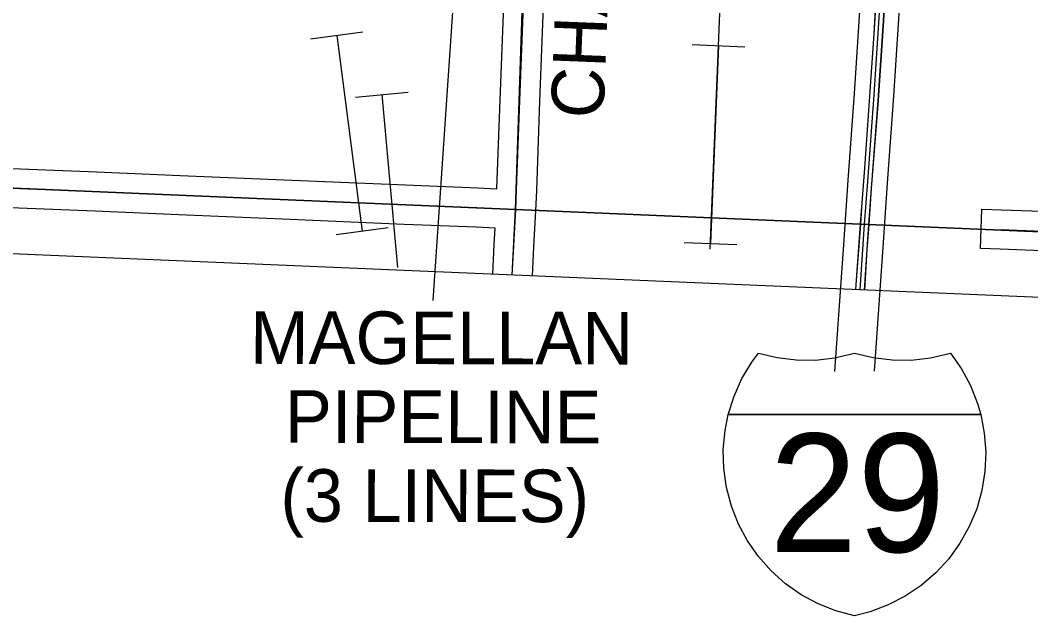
# Model space of a CAD drawing. Extents: x -157.2 to -99.3, y 12.2 to 46.2.
# Drawn here: x -141.844 to -140.306, y 16.458 to 17.364 of the extents above; entities that cross this region are included whole.
import ezdxf

# ---------------------------------------------------------------- set-up
doc = ezdxf.new("R2010")
doc.units = 0
for name, color, linetype in [('tdCoClipBndry', 7, 'Continuous'), ('tdCoCoBndry', 7, 'Continuous'), ('tdCoCoBndryPart', 7, 'Continuous'), ('tdCoDivCarto', 7, 'Continuous'), ('tdCoInt', 7, 'Continuous'), ('tdCoIntCL', 7, 'Continuous'), ('tdCoIntRte', 7, 'Continuous'), ('tdCoPipe', 7, 'Continuous'), ('tdCoPipe1', 7, 'Continuous'), ('tdCoPipe2', 7, 'Continuous'), ('tdCoPipeTxt', 7, 'Continuous'), ('tdCoSecRdTxt', 7, 'Continuous'), ('tdCoSecRteBand', 7, 'Continuous'), ('tdCoSecRteCL', 7, 'Continuous'), ('tdCoSectLine', 7, 'Continuous'), ('tdCoSectLinePart', 7, 'Continuous'), ('tdCoShieldInt', 7, 'Continuous'), ('tdCoSurfAsphalt', 7, 'Continuous'), ('tdCoSurfConc', 7, 'Continuous'), ('tdCoSurfEarth', 7, 'Continuous'), ('tdCoSurfGravel', 7, 'Continuous'), ('tdCoTwpBndryShd', 7, 'Continuous')]:
    doc.layers.add(name, color=color, linetype=linetype)

msp = doc.modelspace()

# ---------------------------------------------------------------- linework, layer by layer
at = {"layer": 'tdCoClipBndry'}
msp.add_lwpolyline([(-136.1344, 16.7663), (-142.0845, 17.0183), (-145.0729, 17.1202)], dxfattribs=at)
at = {"layer": 'tdCoCoBndry'}
msp.add_lwpolyline([(-146.5016, 17.2735), (-146.0768, 17.2556), (-146.0694, 17.2557), (-145.0695, 17.2201), (-144.0702, 17.1857), (-143.0731, 17.1519), (-142.0807, 17.1182), (-141.0904, 17.0763), (-140.1006, 17.0343), (-139.109, 16.9941), (-138.1248, 16.9495), (-137.1248, 16.9061), (-136.1296, 16.8661), (-135.1553, 16.8138), (-134.1666, 16.7512)], dxfattribs=at)
at = {"layer": 'tdCoCoBndryPart'}
msp.add_lwpolyline([(-140.5475, 17.0533), (-140.3822, 17.0463)], dxfattribs=at)
at = {"layer": 'tdCoDivCarto'}
for points in [[(-140.5562, 17.7668), (-140.5483, 17.6739), (-140.5424, 17.6039), (-140.5382, 17.5521), (-140.5372, 17.5151), (-140.5367, 17.4766), (-140.5392, 17.4325), (-140.5414, 17.3999), (-140.5449, 17.3435), (-140.5505, 17.2631), (-140.5592, 17.139), (-140.5631, 17.0865)], [(-140.5562, 17.7668), (-140.5483, 17.6739), (-140.5424, 17.6039), (-140.5382, 17.5521), (-140.5372, 17.5151), (-140.5367, 17.4766), (-140.5392, 17.4325), (-140.5414, 17.3999), (-140.5449, 17.3435), (-140.5505, 17.2631), (-140.5592, 17.139), (-140.5631, 17.0865)], [(-140.5523, 17.0533), (-140.5523, 17.0535), (-140.5484, 17.1082), (-140.5382, 17.2422), (-140.5298, 17.363), (-140.5261, 17.4301), (-140.5236, 17.4666), (-140.5234, 17.4992), (-140.5239, 17.5305), (-140.5251, 17.5583), (-140.5315, 17.6336), (-140.5423, 17.7657), (-140.5425, 17.768)], [(-140.5523, 17.0533), (-140.5523, 17.0535), (-140.5484, 17.1082), (-140.5382, 17.2422), (-140.5298, 17.363), (-140.5261, 17.4301), (-140.5236, 17.4666), (-140.5234, 17.4992), (-140.5239, 17.5305), (-140.5251, 17.5583), (-140.5315, 17.6336), (-140.5423, 17.7657), (-140.5425, 17.768)], [(-140.5631, 17.0865), (-140.5655, 17.0543)], [(-140.5631, 17.0865), (-140.5655, 17.0543)], [(-140.5655, 17.0543), (-140.5655, 17.054), (-140.5723, 16.962), (-140.5728, 16.9543)], [(-140.5655, 17.0543), (-140.5655, 17.054), (-140.5723, 16.962), (-140.5728, 16.9543)], [(-140.559, 16.9537), (-140.555, 17.0154), (-140.5523, 17.0533)], [(-140.559, 16.9537), (-140.555, 17.0154), (-140.5523, 17.0533)]]:
    msp.add_lwpolyline(points, dxfattribs=at)
at = {"layer": 'tdCoInt'}
for points in [[(-140.6042, 16.8299), (-140.5903, 17.0302), (-140.584, 17.1207), (-140.5744, 17.2528), (-140.5628, 17.4333), (-140.5599, 17.4735), (-140.5597, 17.501), (-140.5604, 17.5202), (-140.5618, 17.5511), (-140.5795, 17.7648), (-140.5873, 17.8534), (-140.5902, 17.8858), (-140.5991, 17.9892)], [(-140.544, 16.8304), (-140.5304, 17.026), (-140.5242, 17.1164), (-140.5145, 17.2487), (-140.5029, 17.4293), (-140.4999, 17.4711), (-140.4997, 17.5019), (-140.5004, 17.5227), (-140.5019, 17.555), (-140.5197, 17.77), (-140.5276, 17.8587), (-140.5304, 17.891), (-140.5384, 17.9835)]]:
    msp.add_lwpolyline(points, dxfattribs=at)
at = {"layer": 'tdCoIntCL'}
msp.add_lwpolyline([(-140.5661, 16.954), (-140.5592, 17.0538), (-140.5541, 17.1186), (-140.5445, 17.2507), (-140.5329, 17.4313), (-140.5299, 17.4723), (-140.5297, 17.5015), (-140.5304, 17.5215), (-140.5319, 17.5531), (-140.5496, 17.7674), (-140.5574, 17.856)], dxfattribs=at)
at = {"layer": 'tdCoIntRte'}
for points in [[(-140.5527, 17.0533), (-140.5527, 17.0535), (-140.5487, 17.1082), (-140.5386, 17.2422), (-140.5302, 17.363), (-140.5265, 17.4301), (-140.524, 17.4666), (-140.5238, 17.4992), (-140.5243, 17.5305), (-140.5255, 17.5583), (-140.5319, 17.6336), (-140.5426, 17.7657), (-140.5428, 17.768), (-140.543, 17.7702), (-140.5539, 17.889), (-140.5576, 17.9297), (-140.566, 18.0336), (-140.5662, 18.037), (-140.5696, 18.0792), (-140.5812, 18.2069), (-140.5812, 18.2077), (-140.5889, 18.3009)], [(-140.5527, 17.0533), (-140.5527, 17.0535), (-140.5487, 17.1082), (-140.5386, 17.2422), (-140.5302, 17.363), (-140.5265, 17.4301), (-140.524, 17.4666), (-140.5238, 17.4992), (-140.5243, 17.5305), (-140.5255, 17.5583), (-140.5319, 17.6336), (-140.5426, 17.7657), (-140.5428, 17.768), (-140.543, 17.7702), (-140.5539, 17.889), (-140.5576, 17.9297), (-140.566, 18.0336), (-140.5662, 18.037), (-140.5696, 18.0792), (-140.5812, 18.2069), (-140.5812, 18.2077), (-140.5889, 18.3009)], [(-140.601, 18.2764), (-140.5943, 18.2115), (-140.5939, 18.2058), (-140.5842, 18.0838), (-140.5802, 18.0383), (-140.58, 18.0351), (-140.5714, 17.9368), (-140.5642, 17.8554), (-140.56, 17.8076), (-140.5573, 17.7753), (-140.5566, 17.7668), (-140.5487, 17.6739), (-140.5428, 17.6039), (-140.5386, 17.5521), (-140.5376, 17.5151), (-140.5371, 17.4766), (-140.5396, 17.4325), (-140.5418, 17.3999), (-140.5452, 17.3435), (-140.5509, 17.2631), (-140.5595, 17.139), (-140.5634, 17.0865), (-140.5658, 17.0543)], [(-140.601, 18.2764), (-140.5943, 18.2115), (-140.5939, 18.2058), (-140.5842, 18.0838), (-140.5802, 18.0383), (-140.58, 18.0351), (-140.5714, 17.9368), (-140.5642, 17.8554), (-140.56, 17.8076), (-140.5573, 17.7753), (-140.5566, 17.7668), (-140.5487, 17.6739), (-140.5428, 17.6039), (-140.5386, 17.5521), (-140.5376, 17.5151), (-140.5371, 17.4766), (-140.5396, 17.4325), (-140.5418, 17.3999), (-140.5452, 17.3435), (-140.5509, 17.2631), (-140.5595, 17.139), (-140.5634, 17.0865), (-140.5658, 17.0543)], [(-140.5658, 17.0543), (-140.5658, 17.054), (-140.5727, 16.962), (-140.5732, 16.9543)], [(-140.5658, 17.0543), (-140.5658, 17.054), (-140.5727, 16.962), (-140.5732, 16.9543)], [(-140.5594, 16.9537), (-140.5554, 17.0154), (-140.5527, 17.0533)], [(-140.5594, 16.9537), (-140.5554, 17.0154), (-140.5527, 17.0533)]]:
    msp.add_lwpolyline(points, dxfattribs=at)
at = {"layer": 'tdCoPipe'}
for p, q in [((-140.8217, 17.327), (-140.7413, 17.3238)), ((-140.8338, 17.0261), (-140.7533, 17.0229))]:
    msp.add_line(p, q, dxfattribs=at)
for points in [[(-140.7939, 17.0158), (-140.771, 17.5856), (-141.3809, 20.7773), (-141.4061, 21.2289), (-141.2323, 21.3329), (-141.6198, 22.0977), (-141.6066, 22.6198), (-141.8066, 22.8738), (-141.7898, 23.3819), (-141.8432, 23.4016), (-141.8037, 25.2014)], [(-141.2153, 16.938), (-140.9814, 20.3752), (-141.4436, 21.0626), (-141.5868, 21.3985), (-141.9847, 21.8504), (-142.4211, 22.4672), (-142.8261, 23.0072), (-142.8339, 23.1351), (-143.0775, 23.1591), (-143.0801, 23.5043)], [(-140.7815, 17.3254), (-140.7935, 17.0245)]]:
    msp.add_lwpolyline(points, dxfattribs=at)
at = {"layer": 'tdCoPipe1'}
msp.add_line((-141.3337, 17.2472), (-141.2538, 17.2545), dxfattribs=at)
msp.add_lwpolyline([(-141.2938, 17.2509), (-141.2698, 16.9881)], dxfattribs=at)
at = {"layer": 'tdCoPipe2'}
for p, q in [((-141.402, 17.3358), (-141.3225, 17.3462)), ((-141.3633, 17.0383), (-141.2838, 17.0487))]:
    msp.add_line(p, q, dxfattribs=at)
msp.add_lwpolyline([(-141.3623, 17.341), (-141.3236, 17.0435)], dxfattribs=at)
at = {"layer": 'tdCoSecRteBand'}
for points in [[(-141.1185, 17.1078), (-141.1134, 17.2431), (-141.1134, 17.2431), (-141.1134, 17.2431), (-141.1075, 17.4007), (-141.1014, 17.5648), (-141.0962, 17.7304), (-141.0918, 17.8884), (-141.0918, 17.8884), (-141.0918, 17.8884), (-141.0873, 18.0406), (-141.0873, 18.0406), (-141.0873, 18.0407), (-141.0873, 18.0418), (-141.0875, 18.0418), (-141.096, 18.0422), (-141.096, 18.0422), (-141.0961, 18.0422), (-141.204, 18.0471), (-141.3943, 18.0545), (-141.3944, 18.0545), (-141.3944, 18.0545), (-141.6282, 18.0644), (-141.8548, 18.0737)], [(-141.0476, 17.3984), (-141.0535, 17.2408), (-141.0585, 17.1052), (-141.0585, 17.105), (-141.0585, 17.1048), (-141.0585, 17.1048), (-141.0585, 17.1048), (-141.06, 17.0748), (-141.0627, 17.0197), (-141.0627, 17.0197), (-141.0627, 17.0196), (-141.0651, 16.9751)], [(-141.8955, 17.1403), (-141.7272, 17.1334), (-141.7272, 17.1334), (-141.7271, 17.1334), (-141.6006, 17.128), (-141.4423, 17.1213), (-141.2574, 17.1137), (-141.1477, 17.1092), (-141.1475, 17.1092), (-141.1474, 17.1092), (-141.1185, 17.1078)], [(-141.125, 16.9777), (-141.1226, 17.0228), (-141.1214, 17.0478), (-141.1214, 17.0478), (-141.1502, 17.0493), (-141.2598, 17.0537), (-141.2599, 17.0537), (-141.2599, 17.0537), (-141.4448, 17.0614), (-141.4448, 17.0614), (-141.4448, 17.0614), (-141.6032, 17.068), (-141.6032, 17.068), (-141.6032, 17.068), (-141.7297, 17.0735), (-141.8981, 17.0804), (-141.8982, 17.0804), (-141.8982, 17.0804), (-142.0209, 17.086), (-142.0514, 17.0871), (-142.0518, 17.0871), (-142.0519, 17.0867), (-142.0553, 17.0171)], [(-140.2764, 17.013), (-140.3529, 17.0157), (-140.3829, 17.0168), (-140.3808, 17.0768), (-140.3508, 17.0757), (-140.2741, 17.073)]]:
    msp.add_lwpolyline(points, dxfattribs=at)
at = {"layer": 'tdCoSecRteCL'}
for points in [[(-141.09, 17.0763), (-141.0885, 17.1063), (-141.0835, 17.2419), (-141.0776, 17.3995), (-141.0714, 17.5638), (-141.0662, 17.7295), (-141.0618, 17.8876), (-141.0573, 18.0397), (-141.0564, 18.0706)], [(-142.0803, 17.1182), (-142.0197, 17.116), (-141.8968, 17.1103), (-141.7284, 17.1034), (-141.6019, 17.098), (-141.4436, 17.0913), (-141.2586, 17.0837), (-141.1489, 17.0793), (-141.09, 17.0763)], [(-141.0951, 16.9764), (-141.0927, 17.0212), (-141.09, 17.0763)], [(-140.3519, 17.0457), (-140.2752, 17.043), (-140.1113, 17.0349), (-140.052, 17.0319), (-139.8734, 17.0245), (-139.7504, 17.0198), (-139.6273, 17.0144), (-139.6039, 17.0135)]]:
    msp.add_lwpolyline(points, dxfattribs=at)
at = {"layer": 'tdCoSectLine'}
for points in [[(-141.0904, 17.0763), (-141.0567, 18.0706)], [(-142.0807, 17.1182), (-141.0904, 17.0763)], [(-141.0953, 16.9764), (-141.0904, 17.0763)], [(-141.0904, 17.0763), (-140.1006, 17.0343)]]:
    msp.add_lwpolyline(points, dxfattribs=at)
at = {"layer": 'tdCoSectLinePart'}
msp.add_lwpolyline([(-140.5475, 17.0533), (-140.3822, 17.0463)], dxfattribs=at)
at = {"layer": 'tdCoShieldInt'}
msp.add_line((-140.7633, 16.7647), (-140.386, 16.7647), dxfattribs=at)
for points in [[(-140.5745, 16.4585), (-140.6027, 16.4659), (-140.6298, 16.4767), (-140.6555, 16.4905), (-140.6794, 16.5072), (-140.7012, 16.5266), (-140.7206, 16.5484), (-140.7373, 16.5723), (-140.7511, 16.598), (-140.7618, 16.6251), (-140.7693, 16.6533), (-140.7734, 16.6822), (-140.7741, 16.7113), (-140.7715, 16.7404), (-140.7665, 16.7647), (-140.7577, 16.7925), (-140.7457, 16.8191), (-140.7306, 16.8441), (-140.7204, 16.858), (-140.6921, 16.8511), (-140.6632, 16.8476), (-140.634, 16.8474), (-140.605, 16.8507), (-140.5745, 16.858), (-140.5462, 16.8511), (-140.5172, 16.8476), (-140.4881, 16.8474), (-140.4591, 16.8507), (-140.4286, 16.858), (-140.4119, 16.8341), (-140.398, 16.8084), (-140.3873, 16.7813), (-140.3825, 16.7647), (-140.377, 16.7361), (-140.3748, 16.707), (-140.376, 16.6779), (-140.3807, 16.6491), (-140.3886, 16.621), (-140.3998, 16.5941), (-140.4141, 16.5687), (-140.4312, 16.545), (-140.4509, 16.5236), (-140.473, 16.5046), (-140.4972, 16.4883), (-140.5231, 16.4749), (-140.5504, 16.4646)], [(-140.7665, 16.7647), (-140.7577, 16.7925), (-140.7457, 16.8191), (-140.7306, 16.8441), (-140.7204, 16.858), (-140.6921, 16.8511), (-140.6632, 16.8476), (-140.634, 16.8474), (-140.605, 16.8507), (-140.5745, 16.858), (-140.5462, 16.8511), (-140.5172, 16.8476), (-140.4881, 16.8474), (-140.4591, 16.8507), (-140.4286, 16.858), (-140.4119, 16.8341), (-140.398, 16.8084), (-140.3873, 16.7813), (-140.3825, 16.7647)], [(-140.5745, 16.4585), (-140.6027, 16.4659), (-140.6298, 16.4767), (-140.6555, 16.4905), (-140.6794, 16.5072), (-140.7012, 16.5266), (-140.7206, 16.5484), (-140.7373, 16.5723), (-140.7511, 16.598), (-140.7618, 16.6251), (-140.7693, 16.6533), (-140.7734, 16.6822), (-140.7741, 16.7113), (-140.7715, 16.7404), (-140.7665, 16.7647), (-140.3825, 16.7647), (-140.377, 16.7361), (-140.3748, 16.707), (-140.376, 16.6779), (-140.3807, 16.6491), (-140.3886, 16.621), (-140.3998, 16.5941), (-140.4141, 16.5687), (-140.4312, 16.545), (-140.4509, 16.5236), (-140.473, 16.5046), (-140.4972, 16.4883), (-140.5231, 16.4749), (-140.5504, 16.4646)]]:
    msp.add_lwpolyline(points, close=True, dxfattribs=at)
at = {"layer": 'tdCoSurfAsphalt'}
msp.add_lwpolyline([(-141.0951, 16.9764), (-141.0927, 17.0212), (-141.09, 17.0763)], dxfattribs=at)
at = {"layer": 'tdCoSurfConc'}
msp.add_lwpolyline([(-141.09, 17.0763), (-141.0885, 17.1063), (-141.0835, 17.2419), (-141.0776, 17.3995), (-141.0714, 17.5638), (-141.0662, 17.7295), (-141.0618, 17.8876), (-141.0573, 18.0397), (-141.0564, 18.0706)], dxfattribs=at)
at = {"layer": 'tdCoSurfEarth'}
msp.add_lwpolyline([(-140.3519, 17.0457), (-140.2752, 17.043), (-140.1113, 17.0349)], dxfattribs=at)
at = {"layer": 'tdCoSurfGravel'}
msp.add_lwpolyline([(-142.0803, 17.1182), (-142.0197, 17.116), (-141.8968, 17.1103), (-141.7284, 17.1034), (-141.6019, 17.098), (-141.4436, 17.0913), (-141.2586, 17.0837), (-141.1489, 17.0793), (-141.09, 17.0763)], dxfattribs=at)
at = {"layer": 'tdCoTwpBndryShd'}
for points in [[(-140.5574, 35.0411), (-140.6069, 34.0205), (-140.6476, 33.0243), (-140.68, 32.0266), (-140.7194, 31.0261), (-140.7542, 30.0172), (-140.7866, 29.0316), (-140.7992, 28.0152), (-140.8137, 27.0113), (-140.8321, 26.0183), (-140.8465, 25.0216), (-140.872, 24.0239), (-140.8917, 23.0263), (-140.9324, 22.0454), (-140.9642, 21.0502), (-140.9973, 20.0552), (-141.0197, 19.061), (-141.0567, 18.0706), (-141.0904, 17.0763)], [(-140.1006, 17.0343), (-141.0904, 17.0763), (-142.0807, 17.1182), (-143.0731, 17.1519), (-144.0702, 17.1857), (-145.0695, 17.2201)]]:
    msp.add_lwpolyline(points, dxfattribs=at)

# ---------------------------------------------------------------- texts
at = {"layer": 'tdCoPipeTxt'}
for s, p in [('MAGELLAN', (-141.4942, 16.8416)), ('PIPELINE', (-141.4411, 16.7215)), ('(3 LINES)', (-141.448, 16.6015))]:
    msp.add_text(s, height=0.08, rotation=359.8931, dxfattribs=at).set_placement(p)
at = {"layer": 'tdCoSecRdTxt'}
msp.add_text('CHARLES AVE', height=0.08, rotation=87.7475, dxfattribs=at).set_placement((-140.9567, 17.2137))
at = {"layer": 'tdCoShieldInt'}
msp.add_text('29', height=0.18, dxfattribs=at).set_placement((-140.704, 16.5554))

doc.saveas('drawing.dxf')
